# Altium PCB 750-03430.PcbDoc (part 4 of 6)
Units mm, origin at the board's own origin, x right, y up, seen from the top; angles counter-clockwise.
Board outline 141.61 x 63.5 mm, 6 copper layers (Top Layer, L2, L3, L4, L5, Bottom Layer), stack 1.557 mm thick; 401 components, 285 nets, 1356 pads, 1712 vias.
Unrouted connection lines stored in the file: 45.
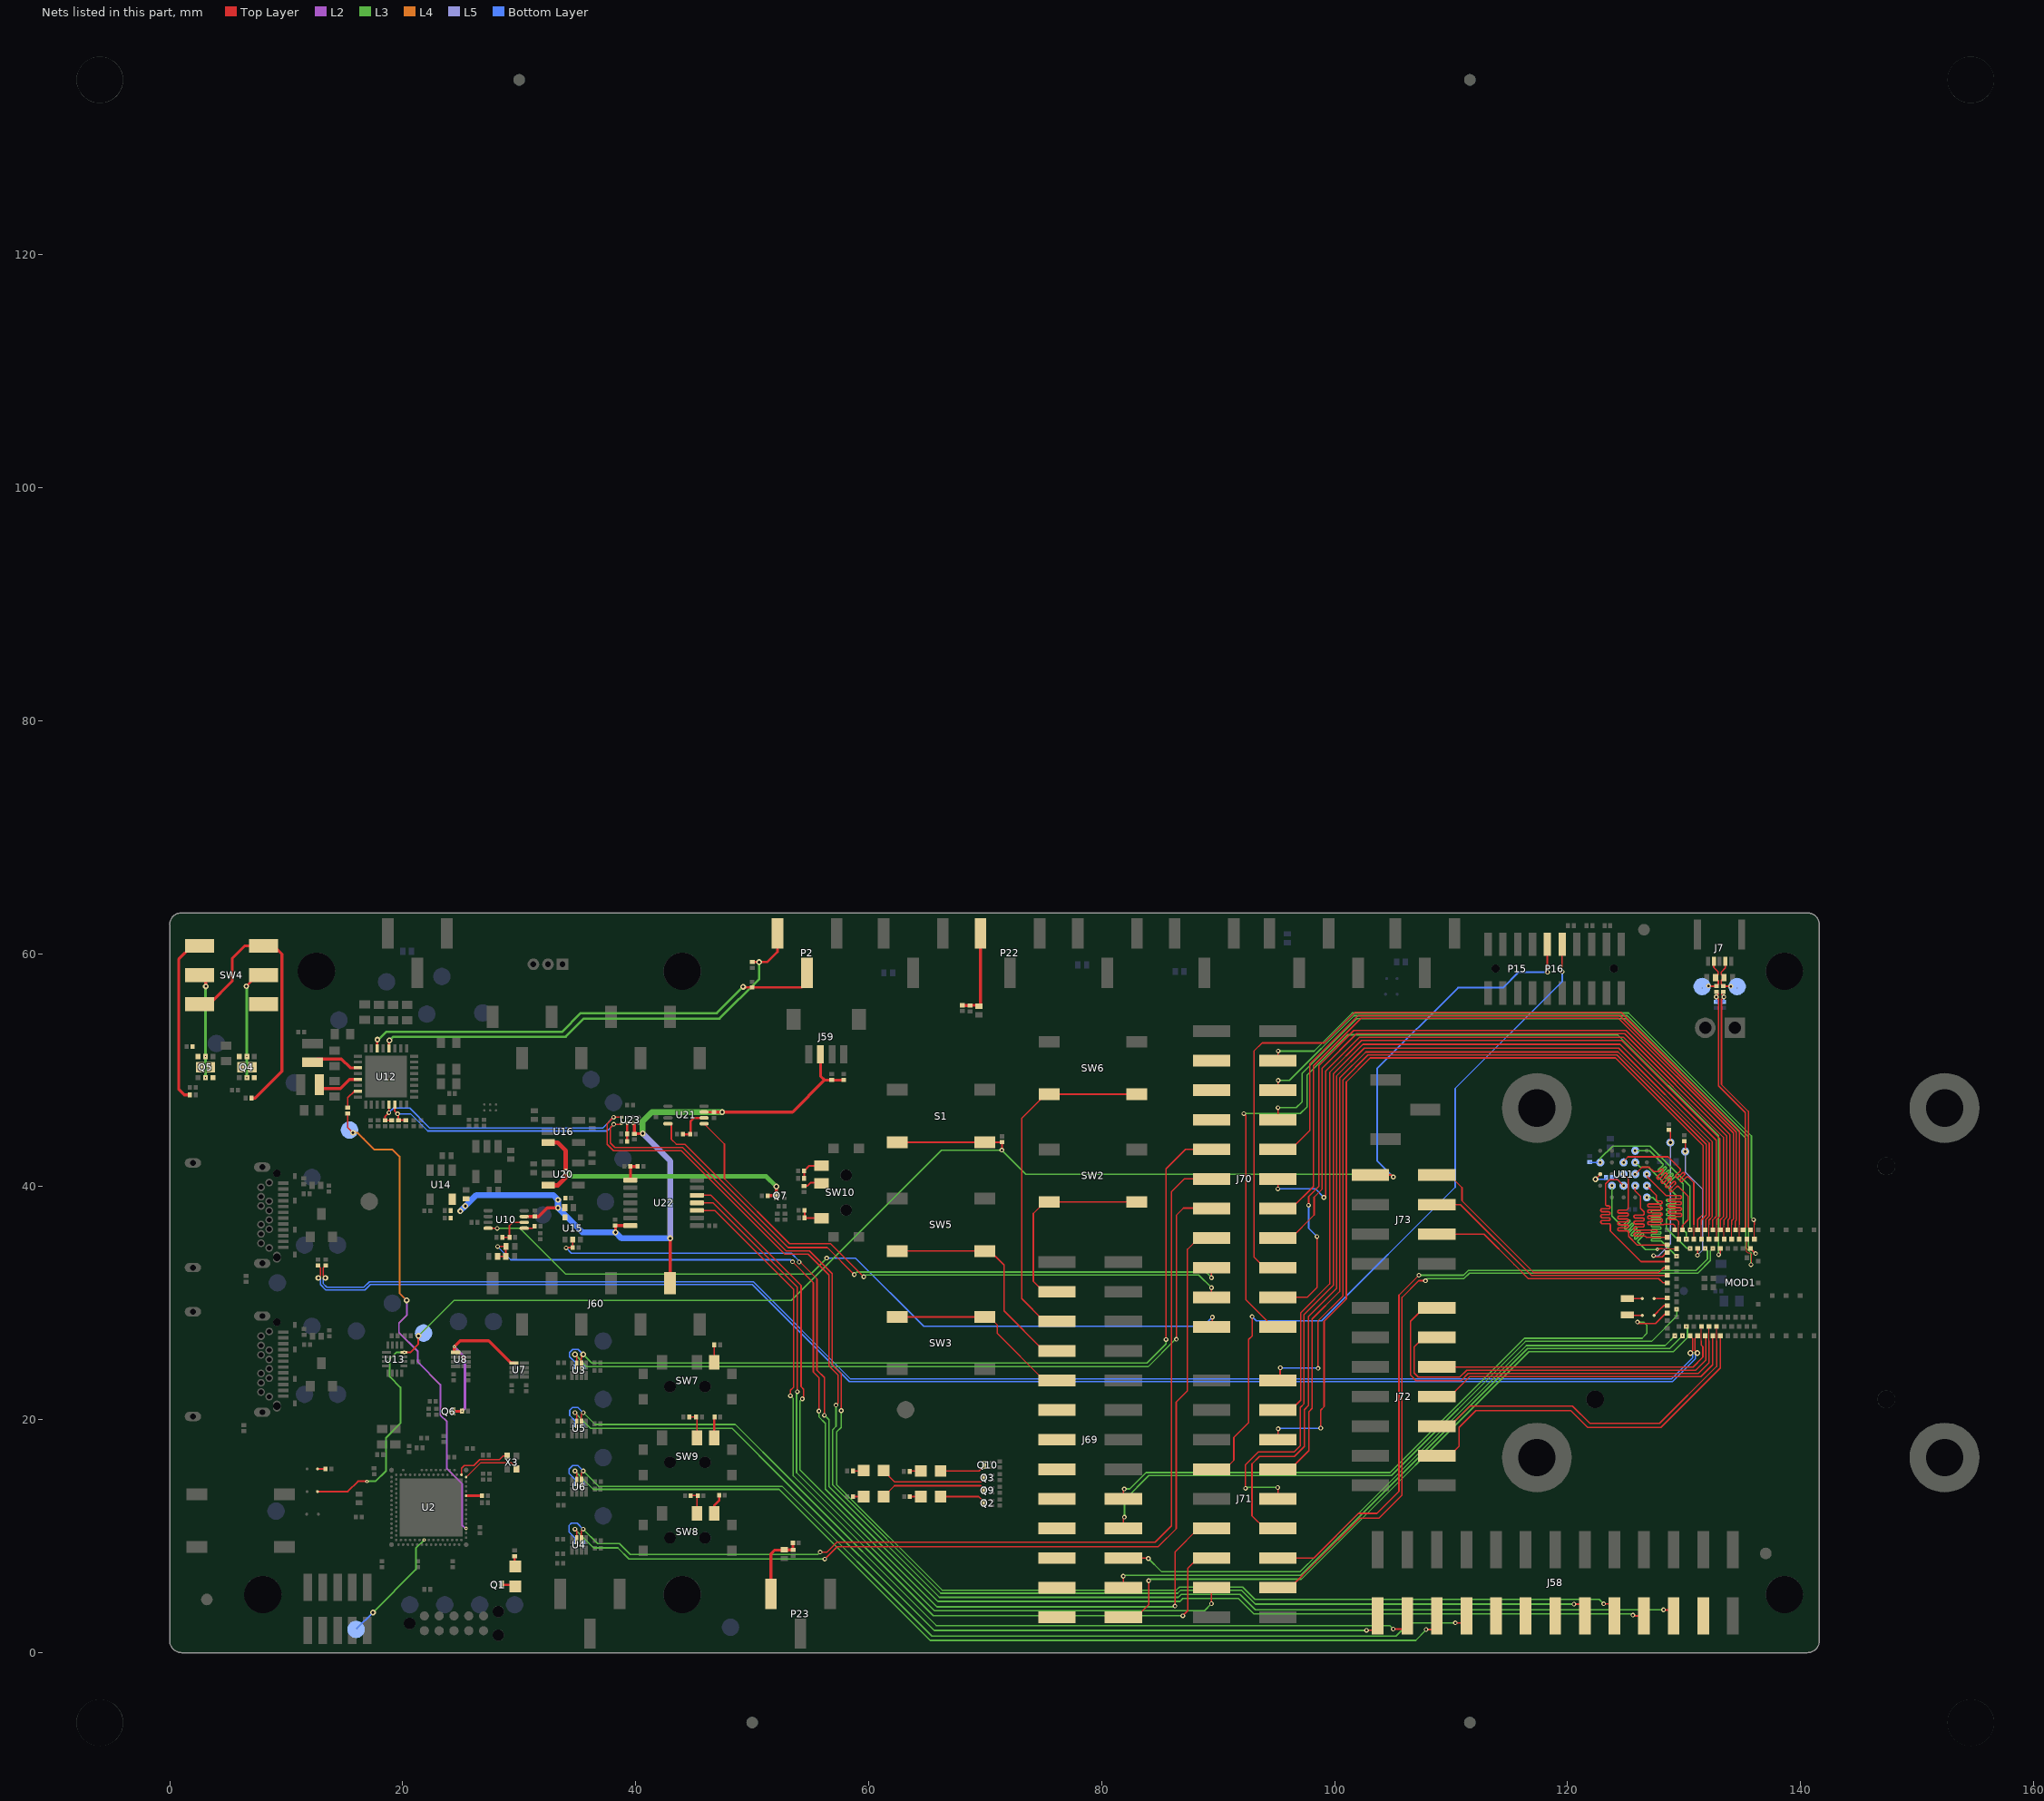
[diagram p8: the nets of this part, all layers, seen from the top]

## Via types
v1: diameter 0.5, hole 0.25, Top Layer to Bottom Layer, tented both sides, 1306 vias
v2: diameter 0.4, hole 0.2, Top Layer to Bottom Layer, tented both sides, 223 vias
v3: diameter 0.3, hole 0.1, Top Layer to L3, tented top, 74 vias
v4: diameter 0.3, hole 0.1, Top Layer to L3, tented both sides, 43 vias
v5: diameter 0.3, hole 0.1, Top Layer to L2, tented both sides, 31 vias
v6: diameter 0.61, hole 0.305, Top Layer to Bottom Layer, tented both sides, 25 vias
v7: diameter 0.3, hole 0.1, Top Layer to L2, tented top, 10 vias

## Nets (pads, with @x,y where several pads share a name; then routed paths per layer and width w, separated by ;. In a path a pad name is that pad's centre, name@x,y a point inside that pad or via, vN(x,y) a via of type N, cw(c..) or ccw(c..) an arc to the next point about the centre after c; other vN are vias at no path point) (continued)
NetJ69_18: J69.18 MOD1.37 | length 56
  Top Layer w0.127: J69.18@81.91,13.161 J69.18@81.868,13.203 81.868,13.977 v2(81.948,14.056) ; v2(125.99,28.376) 126.108,28.258 127.54,28.258 128.432,29.15 MOD1.37@128.559,29.15
  L3 w0.127: v2(81.948,14.056) 82.413,14.056 83.818,15.461 104.768,15.461 116.294,26.987 126.388,26.987 126.811,27.409 126.811,28.117 126.552,28.376 v2(125.99,28.376)
NetJ69_20: J69.20 MOD1.38 | length 57
  Top Layer w0.127: J69.20@81.868,10.663 81.868,11.549 v2(81.96,11.641)
  L3 w0.127: v2(81.96,11.641) 81.96,13.106 84.054,15.2 104.868,15.2 116.389,26.72 127.205,26.72 129.359,28.875 v3(129.359,29.475)
NetJ69_22: J69.22 MOD1.32 | length 56.2
  Top Layer w0.127: J69.22@81.868,8.123 83.968,8.123 v2(84.009,8.081)
  L3 w0.124: v2(84.009,8.081) 85.126,6.965 97.059,6.965 98.426,8.332 116.46,26.365 128.374,26.365 v3(129.209,27.2)
NetJ69_24: J69.24 MOD1.30 | length 57.5
  Top Layer w0.127: v2(81.855,6.562) 81.868,6.549 J69.24@81.868,5.583
  L3 w0.124: v2(81.855,6.562) 81.932,6.638 91.202,6.638 97.092,6.638 116.565,26.111 128.77,26.111 v3(129.859,27.2)
NetJ69_26: J69.26 MOD1.29 | length 60.6
  Top Layer w0.127: J69.26@81.867,3.044 82.95,3.044 84.037,4.132 v2(84.037,6.179)
  L3 w0.124: v2(84.037,6.179) 84.171,6.312 97.144,6.312 116.675,25.844 129.085,25.844 130.29,27.049 130.29,27.894 v3(130.184,28)
NetJ70_4: J70.4 MOD1.88 | length 56.2
  Top Layer w0.076: MOD1.88@136.034,35.5 136.034,36.75
  Top Layer w0.127: J70.4@95.131,50.821 95.131,51.619 v2(95.155,51.642) ; v2(135.962,37.16) 136.031,37.16 136.034,37.157 136.034,36.75
  L3 w0.127: v2(95.155,51.642) 95.158,51.639 98.242,51.639 101.507,54.904 102.547,54.904 125.229,54.904 135.776,44.357 135.776,37.346 v2(135.962,37.16)
NetJ70_6: J70.6 MOD1.86 | length 58.7
  Top Layer w0.102: MOD1.86@135.709,34.7 135.817,34.593 135.817,34.561 136.116,34.261 v2(136.133,34.261)
  Top Layer w0.127: J70.6@95.131,48.281 95.131,49.104 v2(95.156,49.129)
  L3 w0.127: v2(95.156,49.129) 96.122,49.129 101.668,54.675 125.134,54.675 135.532,44.276 135.532,34.845 136.116,34.261 v2(136.133,34.261)
NetJ70_8: J70.8 MOD1.85 | length 63.6
  Top Layer w0.076: MOD1.85@135.384,35.5 135.384,34.414 135.471,34.327 135.616,34.327 135.779,34.165 135.779,33.348 v2(135.739,33.308)
  Top Layer w0.124: J70.8@95.131,45.741 95.131,46.779 v2(95.134,46.782)
  L3 w0.127: v2(95.134,46.782) 96.711,46.782 97.206,47.276 97.206,49.729 101.907,54.429 125.032,54.429 135.297,44.164 135.297,34.746 135.739,34.305 v2(135.739,33.308)
NetJ70_10: J70.10 MOD1.81 | length 60
  Top Layer w0.124: J70.10@95.131,43.201 96.255,43.201 97.869,44.815 97.869,50.552 102.014,54.697 124.466,54.697 134.467,44.695 134.467,37.111 134.409,37.053 MOD1.81@134.409,36.3
NetJ70_12: J70.12 MOD1.75 | length 63
  Top Layer w0.102: MOD1.75@133.109,36.3 133.109,36.75
  Top Layer w0.124: v2(95.127,39.81) 95.131,39.814 J70.12@95.131,40.661 ; v2(99.079,39.081) 99.229,39.23 99.229,49.915 102.152,52.839 124.771,52.839 133.369,44.24 133.369,37.424 133.109,37.164 133.109,36.75
  Bottom Layer w0.124: v2(95.127,39.81) 98.351,39.81 v2(99.079,39.081)
NetJ70_14: J70.14 MOD1.79 | length 64
  Top Layer w0.076: MOD1.79@134.084,35.5 134.084,36.75
  Top Layer w0.124: J70.14@96.28,38.121 98.18,40.021 98.18,50.374 102.265,54.459 124.367,54.459 134.23,44.597 134.23,37.231 134.084,37.085 134.084,36.75
NetJ70_16: J70.16 MOD1.76 | length 65.4
  Top Layer w0.076: MOD1.76@133.434,35.5 133.434,36.75
  Top Layer w0.124: J70.16@95.131,35.581 96.25,35.581 98.243,37.574 98.243,39.105 98.937,39.799 98.937,50.181 101.889,53.133 124.893,53.133 133.664,44.362 133.664,37.383 133.434,37.153 133.434,36.75
NetJ70_18: J70.18 MOD1.82 | length 76.7
  Top Layer w0.076: MOD1.82@134.734,35.5 134.734,36.75
  Top Layer w0.124: J70.18@95.131,33.041 94,33.041 93.069,33.972 93.069,51.629 93.775,52.335 99.11,52.335 101.738,54.963 124.576,54.963 134.734,44.805 134.734,36.75
NetJ70_20: J70.20 MOD1.78 | length 71.9
  Top Layer w0.102: MOD1.78@133.759,36.3 133.759,36.75
  Top Layer w0.124: J70.20@95.131,30.501 97.651,30.501 98.48,31.33 v2(98.48,35.72) ; v2(97.77,38.408) 97.77,39.163 98.639,40.032 98.639,50.387 101.655,53.402 106.388,53.402
  Top Layer w0.127: 106.388,53.402 125.004,53.402 133.933,44.474 133.933,37.306 133.759,37.132 133.759,36.75
  Bottom Layer w0.124: v2(97.77,38.408) 97.77,36.431 v2(98.48,35.72)
NetJ70_22: J70.22 MOD1.74 | length 79.3
  Top Layer w0.102: v2(132.963,34.159) 133.109,34.305 MOD1.74@133.109,34.7
  Top Layer w0.127: v2(92.205,46.271) 92.389,46.087 92.389,30.291 94.719,27.961 J70.22@95.131,27.961
  L3 w0.127: v2(92.205,46.271) 97.054,46.271 97.635,46.852 97.635,49.564 101.112,53.041 124.288,53.041 132.963,44.366 v2(132.963,34.159)
NetJ71_2: J71.2 MOD1.67 | length 73.6
  Top Layer w0.076: MOD1.67@131.484,35.5 131.484,36.75
  Top Layer w0.124: J71.2@95.131,23.364 95.344,23.577 95.323,23.598 v2@95.323,24.476 ; v2@98.556,24.427 98.556,28.468 100.703,30.615
  Top Layer w0.127: 100.703,30.615 100.703,49.145 102.858,51.301 124.223,51.301 131.895,43.629 131.895,37.551 131.484,37.14 131.484,36.75
  Bottom Layer w0.124: v2@95.323,24.476 95.372,24.427 v2@98.556,24.427
  other v2: 98.577,24.406 95.344,24.455
NetJ71_4: J71.4 MOD1.73 | length 78.3
  Top Layer w0.076: MOD1.73@132.784,35.5 132.784,36.75
  Top Layer w0.124: J71.4@95.131,20.824 96.229,20.824 97.083,21.678 97.083,29.173 99.572,31.662 99.572,49.804 102.311,52.543 124.648,52.543 133.074,44.118 133.074,37.455 132.784,37.165 132.784,36.75
NetJ71_6: J71.6 MOD1.66 | length 77.3
  Top Layer w0.102: MOD1.66@131.159,36.3 131.159,36.75
  Top Layer w0.124: J71.6@95.131,18.284 v2@95.131,19.243 ; 101.004,30.358 101.004,48.993 103.059,51.048 124.119,51.048 131.642,43.525 131.642,37.65 131.159,37.167 131.159,36.75
  Top Layer w0.127: v2(98.799,19.275) 98.799,20.814 99.098,21.113 99.098,28.452 101.004,30.358
  Bottom Layer w0.124: v2@95.14,19.252 98.776,19.252 v2(98.799,19.275)
  other v2: 95.152,19.222
NetJ71_8: J71.8 MOD1.69 | length 79.8
  Top Layer w0.102: MOD1.69@131.865,36.3 131.865,36.75
  Top Layer w0.127: J71.8@95.131,15.744 96.194,15.744 97.795,17.346 97.795,20.686 98.074,20.964 98.074,28.648 100.427,31.001 100.427,49.308 102.679,51.56 124.331,51.56 132.154,43.737 132.154,37.472 131.865,37.183 131.865,36.75
NetJ71_10: J71.10 MOD1.72 | length 89.4
  Top Layer w0.102: MOD1.72@132.459,36.3 132.459,36.75
  Top Layer w0.124: v2(92.349,14.109) 92.328,14.13 92.328,16.114 93.434,17.221 96.513,17.221 97.053,17.76 97.053,21.051 97.377,21.376 97.377,29.029 99.882,31.534 99.882,49.664 102.436,52.218 124.514,52.218 132.749,43.983 132.749,37.442 132.459,37.152 132.459,36.75 ; v2@95.095,14.195 95.131,14.16 J71.10@95.131,13.204
  L3 w0.124: v2(92.349,14.109) 92.434,14.195 v2@95.095,14.195
  other v2: 95.116,14.174
NetJ71_12: J71.12 MOD1.70 | length 90.2
  Top Layer w0.076: MOD1.70@132.134,35.5 132.134,36.75
  Top Layer w0.124: J71.12@95.131,10.664 93.995,10.664 92.907,11.752 92.907,16.2 93.551,16.844 96.554,16.844 97.407,17.697 97.407,20.863 97.74,21.196 97.74,28.844 100.154,31.258 100.154,49.503 102.545,51.893 124.379,51.893 132.424,43.848 132.424,37.429 132.134,37.139 132.134,36.75
NetJ71_14: J71.14 MOD1.68 | length 58.4
  Top Layer w0.124: J71.14@95.131,8.124 98.21,8.124 102.046,11.96
  Top Layer w0.127: 102.046,11.96 103.642,11.96 105.52,13.838 105.52,30.689 v2(107.232,32.402)
  L3 w0.127: v2(107.232,32.402) 111.065,32.402 111.475,32.811 114.795,32.811 131.026,32.811 132.004,33.789 132.004,34.505 v3(131.809,34.7)
NetJ71_16: J71.16 MOD1.71 | length 59.8
  Top Layer w0.127: J71.16@95.131,5.584 96.2,5.584 98.362,7.746 102.167,11.551 103.812,11.551 105.788,13.527 105.788,30.497 107.22,31.929 v2(107.799,31.929)
  L3 w0.127: v2(107.799,31.929) 107.967,32.096 111.085,32.096 111.57,32.582 114.7,32.582 131.177,32.582 132.251,33.656 132.251,34.492 v3(132.459,34.7)
NetJ72_2: J72.2 MOD1.20 | length 36.9
  Top Layer w0.076: 132.134,26.75 MOD1.20@132.134,28
  Top Layer w0.127: J72.2@108.77,29.604 107.674,29.604 106.507,28.438 106.507,23.838 106.992,23.353 110.852,23.353 111.47,23.971 131.218,23.971 132.134,24.887 132.134,26.75
NetJ72_4: J72.4 MOD1.22 | length 32.4
  Top Layer w0.102: MOD1.22@131.809,27.2 131.858,27.151 MOD1.22@131.858,27
  Top Layer w0.127: J72.4@108.77,27.064 107.654,27.064 106.833,26.243 106.833,24.003 107.173,23.662 110.744,23.662 111.333,24.252 130.99,24.252 131.858,25.12 MOD1.22@131.858,27
NetJ72_6: J72.6 MOD1.23 | length 25.9
  Top Layer w0.076: 131.484,26.75 MOD1.23@131.484,28
  Top Layer w0.124: J72.6@108.77,24.524 130.771,24.524 131.608,25.362
  Top Layer w0.127: 131.484,26.75 131.484,26.401 131.608,26.277 131.608,25.362
NetJ72_8: J72.8 MOD1.19 | length 27.3
  Top Layer w0.102: 132.459,26.75 MOD1.19@132.459,27.2
  Top Layer w0.127: J72.8@108.77,21.984 109.888,21.984 110.939,23.036 111.599,23.695 131.435,23.695 132.459,24.719 132.459,26.75
NetJ72_10: J72.10 MOD1.17 | length 30.8
  Top Layer w0.076: 132.784,26.75 MOD1.17@132.784,28
  Top Layer w0.127: J72.10@108.77,19.444 109.88,19.444 111.599,21.163 120.422,21.163 121.908,19.677 127.895,19.677 132.784,24.566 132.784,26.75
NetJ72_12: J72.12 MOD1.16 | length 32.4
  Top Layer w0.102: 133.109,26.75 MOD1.16@133.109,27.2
  Top Layer w0.127: J72.12@108.77,16.904 109.872,16.904 110.689,17.722 110.689,19.345 112.121,20.777 120.273,20.777 121.725,19.324 128.002,19.324 133.109,24.432 133.109,26.75
NetJ73_2: J73.2 MOD1.49 | length 24.1
  Top Layer w0.124: 110.935,39.915 110.935,38.79 117.087,32.638
  Top Layer w0.127: J73.2@108.77,40.999 109.851,40.999 110.935,39.915 ; 117.087,32.638 127.822,32.638 128.234,33.05 MOD1.49@128.559,33.05
NetJ73_4: J73.4 MOD1.47 | length 22.3
  Top Layer w0.127: J73.4@108.77,38.459 110.809,38.459 116.891,32.377 128.109,32.377 128.536,32.377 MOD1.47@128.559,32.4
NetJ73_6: J73.6 MOD1.45 | length 21.5
  Top Layer w0.124: 115.408,33.327 116.623,32.112
  Top Layer w0.127: J73.6@108.77,35.919 112.816,35.919 115.408,33.327 ; 116.623,32.112 127.817,32.112 128.179,31.75 MOD1.45@128.559,31.75
NetL7_2: L7.2 U12.3 | length 4.3
  Top Layer w0.254: L7.2@12.324,50.591 12.686,50.953 14.751,50.953 15.504,50.201 U12.3@16.174,50.201
NetL10_2: L10.2 U12.5 | length 3.8
  Top Layer w0.254: L10.2@12.709,48.425 14.662,48.425 15.437,49.2 U12.5@16.174,49.2
NetLED1_1: LED1.1 R5.1 | length 1
  Top Layer w0.2: LED1.1@29.611,7.262 R5.1@29.611,8.258
NetLED1_2: LED1.2 Q1.3 | length 1.1
  Top Layer w0.2: Q1.3@28.514,5.825 28.527,5.812 LED1.2@29.611,5.812
NetLED2_1: LED2.1 R20.1 | length 0.9
  Top Layer w0.127: R20.1@63.541,13.403 63.546,13.397 LED2.1@64.472,13.397
NetLED2_2: LED2.2 Q2.3 | length 4
  Top Layer w0.127: LED2.2@66.172,13.397 69.442,13.397 69.886,12.954 Q2.3@69.886,12.836
NetLED3_1: LED3.1 R21.1 | length 0.9
  Top Layer w0.152: R21.1@58.651,15.597 59.546,15.597 LED3.1@59.582,15.633
NetLED3_2: LED3.2 Q3.3 | length 9.2
  Top Layer w0.127: LED3.2@61.282,15.633 61.282,15.609 62.242,14.649 69.635,14.649 69.886,14.9 Q3.3@69.886,15.017
NetLED4_1: LED4.1 R68.1 | length 0.9
  Top Layer w0.152: R68.1@58.651,13.403 59.577,13.403 LED4.1@59.582,13.397
NetLED4_2: LED4.2 Q9.3 | length 9.3
  Top Layer w0.127: LED4.2@61.282,13.397 62.214,14.329 69.645,14.329 69.886,14.089 Q9.3@69.886,13.926
NetLED5_1: LED5.1 R69.1 | length 1
  Top Layer w0.152: R69.1@63.522,15.564 63.555,15.597 LED5.1@64.472,15.597
NetLED5_2: LED5.2 Q10.3 | length 4
  Top Layer w0.127: LED5.2@66.172,15.597 69.484,15.597 69.886,15.998 Q10.3@69.886,16.108
NetMOD1_39: MOD1.39 SB6.2 | length 1.5
  Top Layer w0.102: 128.109,29.644 128.266,29.8 MOD1.39@128.559,29.8
  Top Layer w0.127: SB6.2@127.418,28.953 128.109,29.644
NetMOD1_41: MOD1.41 SB7.2 | length 1.2
  Top Layer w0.102: 128.109,30.394 128.503,30.394 MOD1.41@128.559,30.45
  Top Layer w0.127: SB7.2@127.418,30.394 128.109,30.394
NetP2_2: P2.2 R105.1 U12.30 | length 40.5
  Top Layer w0.203: U12.30@17.823,51.85 17.823,52.615 v1(17.829,52.62) ; v1(49.22,57.156) 49.284,57.092 R105.1@49.988,57.092 54.238,57.092 54.716,57.57 P2.2@54.716,58.355
  L3 w0.203: v1(17.829,52.62) 17.922,52.62 18.589,53.286 33.661,53.286 35.263,54.888 46.953,54.888 v1(49.22,57.156)
NetP2_3: P2.3 R88.1 U12.28 | length 40.2
  Top Layer w0.203: U12.28@18.824,51.85 18.824,52.513 v1(18.858,52.546) ; R88.1@50.009,59.269 50.012,59.272 v1(50.594,59.272) 51.292,59.272 52.176,60.156 P2.3@52.176,61.755
  L3 w0.203: v1(18.858,52.546) 19.183,52.871 33.99,52.871 35.541,54.422 47.196,54.422 50.613,57.84 50.613,59.254 v1(50.594,59.272)
NetP22_3: P22.3 R35.1 R97.2 R101.1 | length 7.7
  Top Layer w0.254: R101.1@68.048,55.569 68.057,55.559 R97.2@68.709,55.559 ; R97.2@68.721,55.571 69.392,55.571 R35.1@69.462,55.501 69.597,55.636 P22.3@69.597,61.755
NetP23_3: P23.3 R37.1 R98.2 R102.1 | length 6.1
  Top Layer w0.254: P23.3@51.605,5.034 51.605,8.471 51.942,8.807 52.732,8.807 R37.1@52.757,8.832 R98.2@53.505,8.832 ; R102.1@53.499,9.431 53.499,8.838 R98.2@53.505,8.832 ; R98.2@53.524,8.812 R98.2@53.505,8.832
NetQ4_2: Q4.2 Q4.5 SW4.5 | length 9.8
  Top Layer w0.254: v1(6.578,57.202) 7.545,58.169 SW4.5@8.072,58.169
  L3 w0.254: v1(6.578,57.202) 6.624,57.157 v3(6.624,51.162) v3(6.624,49.352)
NetQ4_3: Q4.3 Q4.6
NetQ5_2: Q5.2 Q5.5 SW4.2 | length 9
  Top Layer w0.254: SW4.2@2.572,58.169 3.102,57.639 v1(3.102,57.193)
  L3 w0.254: v3(3.075,49.353) v3(3.075,51.163) 3.075,57.166 v1(3.102,57.193)
NetQ5_3: Q5.3 Q5.6 R27.1 SW4.6
NetQ6_3: Q6.3 R19.1 U7.5 U8.5 | length 13.5
  Top Layer w0.125: R19.1@25.059,20.717 R19.1@25.086,20.743
  Top Layer w0.254: Q6.3@24.321,20.717 R19.1@25.059,20.717 ; U8.5@24.545,25.771 24.426,25.89 v5(24.426,26.265) 24.94,26.778 27.374,26.778 29.288,24.864 U7.5@29.545,24.864
  L2 w0.254: v5@24.413,26.265 25.342,25.336 25.342,20.985 v5(25.086,20.73)
NetQ7_3: Q7.3 R36.2 U16.3 U20.3 | length 26
  Top Layer w0.254: R36.2@51.353,39.223 51.356,39.226 Q7.3@52.072,39.226 52.072,39.999 v1(52.079,40.007)
  Top Layer w0.381: U20.3@32.487,40.123 33.328,40.123 33.997,40.792 v1(33.997,41.286) 33.997,43.091 33.298,43.79 U16.3@32.496,43.79
  L3 w0.381: v1(33.997,41.286) 34.394,40.89 51.197,40.89 v1(52.079,40.007)
NetR7_1: R7.1 U2.L31 | length 1.3
  Top Layer w0.2: U2.L31@25.445,13.474 R7.1@26.76,13.474
NetR12_1: R12.1 SW8.3 | length 1.7
  Top Layer w0.203: SW8.3@46.753,11.961 46.753,12.653 47.157,13.056 R12.1@47.157,13.505
NetR13_1: R13.1 SW9.3 | length 1.8
  Top Layer w0.203: SW9.3@46.753,18.441 R13.1@46.753,20.211
NetR14_1: R14.1 R118.1 SW10.3 | length 2.3
  Top Layer w0.15: R118.1@54.465,40.71 R14.1@54.465,41.355 54.901,41.791 SW10.3@55.969,41.791
NetR22_2: R22.2 SB1.2 | length 0.7
  Top Layer w0.15: SB1.2@12.682,15.773 SB1.2@12.682,15.773 R22.2@13.385,15.772
NetR26_2: R26.2 SW4.3 SW4.4 | length 24.2
  Top Layer w0.254: SW4.3@2.572,55.669 3.391,55.669 5.371,57.649 5.371,59.612 6.427,60.669 SW4.4@8.072,60.669 8.939,60.669 9.641,59.967 9.641,49.907 7.345,47.612 R26.2@7.016,47.612
NetR28_1: R28.1 U11.A3 | length 1.6
  Top Layer w0.127: v1(122.388,40.639) 122.803,41.055 U11.A3@122.803,41.079
  Bottom Layer w0.127: v1(122.388,40.639) 123.167,40.639 R28.1@123.313,40.785
NetR38_1: R38.1 SW7.3 | length 1.5
  Top Layer w0.127: R38.1@46.739,26.421 46.753,26.407 SW7.3@46.753,24.937
NetR64_1: R64.1 SW4.1 | length 14.6
  Top Layer w0.254: R64.1@1.719,47.878 1.255,47.878 0.783,48.351 0.783,59.544 1.908,60.669 SW4.1@2.572,60.669
NetR75_1: R75.1 R80.1 U10.6 | length 3
  Top Layer w0.127: R75.1@28.571,35.648 R80.1@29.164,35.648 29.164,36.649 29.45,36.936 U10.6@30.431,36.936
NetR76_1: R76.1 R92.1 U21.6 | length 3
  Top Layer w0.203: R76.1@44.068,44.502 R92.1@44.662,44.502 44.709,44.549 44.709,45.619 44.996,45.905 U21.6@45.871,45.905
NetR77_1: R77.1 R93.1 U22.8 | length 1.8
  Top Layer w0.254: U22.8@39.554,40.561 39.554,41.731 R93.1@39.551,41.735 R77.1@40.171,41.735
NetR78_1: R78.1 R94.1 U23.C2 | length 1.6
  Top Layer w0.203: R94.1@39.269,43.898 39.263,43.904 R78.1@39.263,44.528 39.273,44.538 U23.C2@39.273,45.468
NetR109_1: R109.1 R110.1 SW8.2 | length 2.1
  Top Layer w0.127: R109.1@44.736,13.485 R110.1@45.326,13.485 45.253,13.412 SW8.2@45.253,11.961
NetR111_1: R111.1 R112.1 SW9.2 | length 2.4
  Top Layer w0.127: R111.1@44.597,20.226 R112.1@45.188,20.226 45.253,20.161 SW9.2@45.253,18.441
NetR113_1: R113.1 SW10.2 | length 1.7
  Top Layer w0.15: R113.1@54.447,40.058 54.722,40.058 55.021,40.357 55.903,40.357 SW10.2@55.969,40.291
NetR117_1: R117.1 R119.1 SW10.1 | length 2.1
  Top Layer w0.15: R117.1@54.504,37.973 54.508,37.969 R119.1@54.508,37.319 54.536,37.291 SW10.1@55.969,37.291
NetR120_2: R120.2 U12.7 | length 2
  Top Layer w0.152: R120.2@15.28,46.793 15.28,47.633 15.846,48.199 U12.7@16.174,48.199
NetR122_2: R122.2 U10.5 | length 1
  Top Layer w0.127: U10.5@30.431,36.436 31.153,36.436 R122.2@31.326,36.609
NetSB6_1: SB6.1 X2.2 | length 1.3
  Top Layer w0.127: X2.2@125.122,29.003 125.173,28.953 SB6.1@126.418,28.953
NetSB7_1: SB7.1 X2.1 | length 1.3
  Top Layer w0.127: X2.1@125.122,30.403 125.132,30.394 SB7.1@126.418,30.394
NetTP40_1: TP40.1 U2.AK14 | length 10
  L3 w0.152: v1@17.445,3.454 21.132,7.141 21.132,8.961 v3(21.845,9.674)
  Bottom Layer w0.152: TP40.1@16.066,2.069 v1@17.447,3.45
  other v1: 17.447,3.454
NetU2_B30: U2.B30 X3.3 | length 4.9
  Top Layer w0.125: U2.B30@25.045,15.274 25.045,15.822 25.284,16.062 26.103,16.062 26.603,16.562 28.303,16.562 28.62,16.879 X3.3@28.97,16.879
NetU2_C31: U2.C31 X3.1 | length 5.3
  Top Layer w0.125: U2.C31@25.445,15.074 25.469,15.074 26.707,16.312 29.304,16.312 29.945,15.671 X3.1@29.945,15.604
NFC1: C65.1 J7.2 R24.1 TP19.1 | length 3.1
  Top Layer w0.127: C65.1@133.343,58.051 133.183,58.211 133.183,58.407 133.548,58.772 J7.2@133.548,59.341 ; C65.1@133.418,57.942 133.19,57.714 133.19,57.373 R24.1@133.355,57.209 133.371,57.224 133.394,57.2 v2(134.004,57.2)
  Bottom Layer w0.127: TP19.1@134.537,57.053 TP19.1@134.542,57.053
NFC2: C66.1 J7.4 R25.1 TP20.1 | length 3.1
  Top Layer w0.127: v2(132.096,57.238) 132.125,57.209 R25.1@132.791,57.209 132.936,57.353 132.936,57.704 C66.1@132.699,57.942 ; J7.4@132.548,59.341 132.548,58.817 132.929,58.436 132.929,58.201 C66.1@132.779,58.051
  Bottom Layer w0.127: TP20.1@131.542,57.053 TP20.1@131.552,57.053
nPM1300_R\E\S\E\T\: R120.1 TP11.1 U2.AE31 | length 41.5
  Top Layer w0.152: R120.1@15.28,46.293 15.28,45.082 v1(15.738,44.624)
  L2 w0.152: v1@20.366,30.226 20.366,28.981 19.68,28.296 19.68,27.483 21.306,25.857 21.306,24.943 23.236,23.012 23.236,20.399 23.794,19.841 23.794,15.79 25.116,14.468 25.116,10.922 25.363,10.674 v7(25.445,10.674)
  L4 w0.152: v1(15.738,44.624) 16.139,44.624 16.66,44.103 17.586,43.176 19.131,43.176 19.723,42.584 19.723,30.867 v1(20.335,30.254)
nRF54_N: MOD1.28 R43.1 | length 126
  Top Layer w0.119: v1@13.315,32.22 13.169,32.366 13.169,33.018 R43.1@13.388,33.237 ; MOD1.28@130.509,27.2 130.724,26.986 130.724,25.912 v1@130.585,25.773
  Bottom Layer w0.119: v1@13.315,32.22 13.166,32.071 13.166,31.688 13.492,31.362 16.672,31.362 17.14,31.83 50.105,31.83 58.444,23.492 128.91,23.492 130.73,25.312 130.73,25.628 v1@130.585,25.773
  other v1: 130.538,25.726 13.363,32.167
nRF54_P: MOD1.25 R44.1 | length 126.7
  Top Layer w0.119: R44.1@12.73,33.237 12.948,33.018 12.948,32.364 v1@12.804,32.22 ; v1@131.096,25.773 130.945,25.925 130.945,26.986 MOD1.25@131.159,27.2
  Bottom Layer w0.119: v1@12.804,32.22 12.945,32.079 12.945,31.597 13.401,31.141 16.764,31.141 17.232,31.61 50.014,31.61 58.352,23.271 129.001,23.271 130.951,25.221 130.951,25.628 v1@131.096,25.773
  other v1: 131.138,25.726 12.762,32.167
nRF54H20_RESET: C9.1 J73.1 P15.10 P16.10 S1.3 S1.4 SB3.2 TP61.1 U13.12 | length 154.2
  Top Layer w0.152: SB3.2@12.682,13.831 15.284,13.831 16.17,14.717 v3@16.926,14.717 ; v4(20.141,25.777) 20.645,25.777 21.351,26.484 v1(21.351,27.189) ; S1.3@62.462,43.814 S1.4@69.962,43.814 71.457,43.814 C9.1@71.458,43.815 71.458,43.162 v2(71.431,43.136) ; J73.1@103.07,40.999 104.879,40.999 105.037,40.841 v2(105.037,40.83) ; P15.10@118.256,60.816 118.256,58.433 v2(118.278,58.411)
  L3 w0.127: v1(21.351,27.189) 24.41,30.249 53.358,30.249 66.245,43.136 v2(71.431,43.136)
  L3 w0.152: v3@16.926,14.717 v3(16.937,14.707) 17.673,14.707 18.57,15.603 18.57,18.448 19.807,19.685 19.807,22.775 18.893,23.689 18.893,25.222 19.448,25.777 v4(20.141,25.777) ; v2(71.431,43.136) 73.503,41.065 104.813,41.065 105.037,40.841 v2(105.037,40.83)
  Bottom Layer w0.152: v2(105.037,40.83) 103.65,42.217 103.65,50.138 110.593,57.08 114.466,57.08 115.797,58.411 v2(118.278,58.411)
P0.00: J69.23
P0.01: J69.17
P0.02: J69.19
P0.03: J69.21
P0.04: J69.25
P0.05: J69.11
P0.06: J69.15
P0.07: J69.13
P0.08: J69.3 SW2.3 SW2.4 | length 17.5
  Top Layer w0.127: J69.3@76.168,30.983 75.026,30.983 74.134,31.875 74.134,37.698 75.123,38.687 SW2.3@75.504,38.687 SW2.4@83.004,38.687
P0.09: J69.9 SW3.3 SW3.4 | length 16.7
  Top Layer w0.127: SW3.4@62.462,28.815 SW3.3@69.962,28.815 70.349,28.815 71.054,28.11 71.054,27.386 75.077,23.363 J69.9@75.856,23.363 ; J69.9@75.856,23.363 J69.9@76.168,23.363 J69.9@75.856,23.363
P0.10: J69.7 SW5.3 SW5.4 | length 20.7
  Top Layer w0.127: SW5.3@62.462,34.476 SW5.4@69.962,34.476 70.423,34.476 71.621,33.278 71.621,29.337 75.055,25.903 J69.7@76.168,25.903 75.829,25.903 J69.7@75.057,25.903
P0.11: J69.5 SW6.3 SW6.4 | length 31.1
  Top Layer w0.127: J69.5@75.083,28.443 75.855,28.443 J69.5@76.168,28.443 75.075,28.443 73.133,30.385 73.133,45.871 75.198,47.937 SW6.3@75.504,47.937 SW6.4@83.004,47.937
P1.00: C21.2 J58.8 R33.1 R48.2 | length 123.8
  Top Layer w0.124: v2(28.147,34.856) 28.173,34.882 C21.2@28.868,34.882 28.852,34.866 R48.2@28.852,34.011 28.842,34.022 R33.1@28.148,34.022 ; 55.254,24.082 55.724,23.612 v2(55.724,20.735) ; v2(125.608,3.23) 125.682,3.156 J58.8@126.558,3.156
  Top Layer w0.125: v2(53.46,33.561) 55.254,31.768 55.254,24.082
  L3 w0.124: v2(55.724,20.735) 55.724,20.255 56.291,19.688 56.291,14.049 65.935,4.406 86.727,4.406 86.972,4.651 91.73,4.651 93.06,3.321 125.516,3.321 v2(125.608,3.23)
  Bottom Layer w0.125: v2(28.147,34.856) 29.282,33.721 53.301,33.721 v2(53.46,33.561)
P1.01: J58.6 R87.2 U15.2 | length 119.8
  Top Layer w0.124: v2(34.032,34.746) 34.058,34.773 R87.2@34.6,34.773 34.598,34.774 U15.2@34.598,35.467 ; v2(54.035,33.527) 54.117,33.527 55.563,32.082 55.563,24.244 56.199,23.608 v2(56.199,20.379) ; v2(128.228,3.686) 128.249,3.664 129.098,3.664 J58.6@129.098,3.156
  L3 w0.124: v2(56.199,20.379) 56.587,19.991 56.587,14.249 66.08,4.756 86.587,4.756 86.832,5.002 91.875,5.002 93.191,3.686 v2(128.228,3.686)
  Bottom Layer w0.124: v2(34.032,34.746) 34.486,34.292 53.352,34.292 54.035,33.609 v2(54.035,33.527)
P1.02: J58.4 | length 1.2
  Top Layer w0.124: J58.4@131.519,4.331 131.638,4.212 J58.4@131.638,3.156
P1.03: J58.10 R99.2 R107.2 U12.14 U23.D2 | length 138.3
  Top Layer w0.124: v2(123.086,4.199) 123.814,4.199 124.018,3.996 J58.10@124.018,3.156
  Top Layer w0.127: U23.D2@38.773,45.468 38.659,45.354 v2(38.117,45.354) 37.829,45.066 37.829,43.755 38.224,43.36 44.034,43.36 52.908,34.486 54.93,34.486 56.869,32.547 56.869,24.724 57.647,23.946 v2(57.647,20.774)
  Top Layer w0.15: U12.14@19.325,47.05 19.324,46.494 v2(19.563,46.255) 19.63,46.189 R107.2@19.63,45.709 ; R107.2@19.642,45.697 19.649,45.705 R99.2@20.266,45.705
  L3 w0.124: v2(57.647,20.774) 57.647,19.346 57.259,18.958 57.259,14.417 66.307,5.369 86.407,5.369 86.677,5.638 92.105,5.638 93.162,4.582 122.547,4.582 122.704,4.582 v2(123.086,4.199)
  Bottom Layer w0.127: v2(19.563,46.255) 20.681,46.255 22.152,44.784 37.547,44.784 v2(38.117,45.354)
P1.04: J58.12 R100.2 R106.1 U12.13 U23.D1 | length 138.1
  Top Layer w0.124: v2(120.545,4.171) J58.12@121.477,4.171 ; J58.12@121.478,3.156 J58.12@121.478,4.171
  Top Layer w0.127: U23.D1@38.773,45.968 38.115,45.968 v2(38.105,45.959) 37.547,45.4 37.547,43.639 38.107,43.078 43.917,43.078 52.791,34.204 54.813,34.204 56.587,32.43 56.587,24.607 57.366,23.827 57.366,21.422 v2@57.212,21.268
  Top Layer w0.15: U12.13@18.824,47.05 18.824,46.361 v2(18.812,46.348) 18.502,46.039 18.502,45.692 18.509,45.699 R106.1@19.061,45.699
  L3 w0.124: v2@57.212,21.268 v2(57.196,21.252) 57.196,19.429 56.917,19.149 56.917,14.38 66.196,5.101 86.519,5.101 86.788,5.37 91.994,5.37 93.194,4.171 v2(120.545,4.171)
  Bottom Layer w0.127: v2(18.812,46.348) 19.203,46.74 20.607,46.74 22.307,45.04 37.187,45.04 v2(38.105,45.959)
P1.05: J58.14
P1.06: J58.16
P1.07: J58.20 R59.1 U6.6 | length 86.7
  Top Layer w0.124: U6.6@35.345,14.696 35.345,15.443 v2(35.5,15.599) ; v2(110.357,2.568) 110.386,2.539 111.111,2.539 111.318,2.745 J58.20@111.318,3.156
  L3 w0.124: v2(35.5,15.599) 36.814,14.285 52.563,14.285 65.424,1.424 105.266,1.424 106.41,2.568 v2(110.357,2.568)
  Bottom Layer w0.124: R59.1@34.817,14.459 34.817,14.855 34.288,15.384 34.288,15.763 34.587,16.062 35.037,16.062 v2(35.5,15.599)
P1.08: J58.18
P1.09: J58.22 R58.1 U6.7 | length 84
  Top Layer w0.124: v2(34.789,15.599) 34.945,15.443 U6.7@34.945,14.696 ; v2(107.846,1.986) 108.788,1.986 108.788,3.145 J58.22@108.778,3.156
  L3 w0.124: v2(34.789,15.599) 36.364,14.024 52.301,14.024 65.271,1.054 106.959,1.054 107.846,1.941 v2(107.846,1.986)
  Bottom Layer w0.124: v2(34.789,15.599) 35.471,14.917 R58.1@35.471,14.455
P1.10: J58.24 R57.1 U5.6 | length 83.4
  Top Layer w0.124: v2(105.026,2.025) 106.112,2.025 106.238,2.151 J58.24@106.238,3.156
  Top Layer w0.127: U5.6@35.345,19.696 35.345,20.443 v2(35.5,20.599)
  L3 w0.124: v2(35.5,20.599) 36.513,19.587 48.549,19.587 53.207,14.929 65.801,2.334 104.716,2.334 v2(105.026,2.025)
  Bottom Layer w0.127: R57.1@34.827,19.527 34.827,19.884 34.34,20.372 34.34,20.815 34.575,21.051 35.049,21.051 v2(35.5,20.599)
P1.11: J58.26 R56.1 U5.7 | length 80.1
  Top Layer w0.124: v2(102.739,1.917) 103.551,1.917 103.699,2.065 J58.26@103.699,3.157
  Top Layer w0.127: v2(34.789,20.599) 34.945,20.443 U5.7@34.945,19.696
  L3 w0.124: v2(34.789,20.599) 36.13,19.258 48.274,19.258 52.905,14.627 65.624,1.908 102.73,1.908 v2(102.739,1.917)
  Bottom Layer w0.127: v2(34.789,20.599) 35.466,19.922 R56.1@35.466,19.527
P2.00: J70.5 | length 0.6
  Top Layer w0.127: J70.5@89.018,48.694 J70.5@89.431,48.281
P2.01: J70.3 | length 1.1
  Top Layer w0.125: J70.3@88.338,50.821 J70.3@89.431,50.821
P2.02: J70.7 | length 1.1
  Top Layer w0.127: J70.7@88.334,45.741 J70.7@89.431,45.741
P2.03: J70.21 U10.4 | length 68
  Top Layer w0.127: U10.4@27.331,36.436 28.09,36.436 v2(28.109,36.417) ; J70.21@89.431,27.961 89.506,28.036 v2(89.506,28.802)
  L3 w0.127: v2(28.109,36.417) 30.074,36.417 33.99,32.501 55.03,32.501 v2(56.395,33.866)
  Bottom Layer w0.127: v2(56.395,33.866) 58.878,33.866 64.731,28.014 88.718,28.014 v2(89.506,28.802)
P2.04: J70.9 R53.1 U3.6 | length 74.5
  Top Layer w0.125: U3.6@35.345,24.696 35.345,25.443 v1(35.5,25.599) ; v2(85.53,26.876) 85.53,41.529 87.202,43.201 J70.9@89.431,43.201
  L3 w0.125: v1(35.5,25.599) 36.234,24.865 83.888,24.865 85.53,26.507 v2(85.53,26.876)
  Bottom Layer w0.125: R53.1@34.842,24.535 34.842,24.903 34.324,25.421 34.324,25.769 34.597,26.041 35.058,26.041 v1(35.5,25.599)
P2.05: J70.11 R55.1 U4.6 | length 89.2
  Top Layer w0.127: U4.6@35.345,9.696 35.345,10.443 v2(35.5,10.599) ; v2(55.833,8.642) 56.428,8.642 57.279,9.493 84.586,9.493 85.988,10.895 85.988,39.569 87.08,40.661 J70.11@89.431,40.661
  L3 w0.127: v2(35.5,10.599) 36.737,9.362 38.615,9.362 39.534,8.443 55.634,8.443 v2(55.833,8.642)
  Bottom Layer w0.127: R55.1@34.809,9.477 34.809,9.831 34.27,10.37 34.27,10.904 34.477,11.111 34.988,11.111 v2(35.5,10.599) v2@35.45,10.548
P2.06: J70.13 R52.1 U3.7 | length 70.3
  Top Layer w0.125: v1(34.789,25.599) 34.945,25.443 U3.7@34.945,24.696 ; v2(86.407,26.906) 86.407,37.546 87.022,38.16 89.392,38.16 J70.13@89.431,38.121 J70.13@88.384,38.121
  L3 w0.125: v1(34.789,25.599) 35.847,24.541 83.986,24.541 86.35,26.906 v2(86.407,26.906)
  Bottom Layer w0.125: v1(34.789,25.599) 35.49,24.898 R52.1@35.49,24.528
P2.07: J70.15 R54.1 U4.7 | length 83
  Top Layer w0.124: v2(34.789,10.599) 34.945,10.443 U4.7@34.945,9.696
  Top Layer w0.125: v2(56.234,8.034) 57.289,9.089 84.853,9.089 86.404,10.64 86.404,21.52 87.368,22.484 87.368,34.624 88.325,35.581 J70.15@89.431,35.581
  L3 w0.127: v2(34.789,10.599) 36.393,8.995 38.464,8.995 39.425,8.034 v2(56.234,8.034)
  Bottom Layer w0.127: v2(34.789,10.599) 35.45,9.938 R54.1@35.45,9.477
P2.08: J70.19 U21.5 | length 52.1
  Top Layer w0.124: U21.5@45.871,45.405 47.622,43.654 47.622,40.692 53.215,35.099 56.738,35.099 v2(59.578,32.259) ; v2(89.426,31.329) 89.431,31.324 J70.19@89.431,30.501
  L3 w0.124: v2(59.578,32.259) 59.737,32.418 88.337,32.418 v2@89.431,31.324
P2.09: J70.17 U21.4 | length 53.9
  Top Layer w0.124: U21.4@42.771,45.405 43.017,45.405 43.061,45.361 43.061,44.07 43.483,43.648 44.213,43.648 53.09,34.772 56.453,34.772 v2(58.762,32.463) ; v2(89.431,32.19) J70.17@89.431,33.041
  L3 w0.124: v2(58.762,32.463) 58.974,32.674 88.947,32.674 v2(89.431,32.19)
P2.10/NFC_N: MOD1.87 R24.2 R70.1 | length 22.1
  Top Layer w0.127: R24.2@133.355,56.709 133.22,56.574 133.22,56.46 133.394,56.287 v2(133.408,56.287) 133.205,56.084 133.205,48.761 135.512,46.454 135.512,36.497 MOD1.87@135.709,36.3
  Bottom Layer w0.127: R70.1@133.4,55.856 133.408,55.864 v2(133.408,56.287)
P2.11/NFC_P: MOD1.84 R4.1 R25.2 | length 22.1
  Top Layer w0.127: R25.2@132.791,56.709 132.926,56.574 132.926,56.462 v2(132.754,56.291) 132.951,56.094 132.951,48.656 135.258,46.349 135.258,39.572 ; MOD1.84@135.059,36.3 135.258,36.499 135.258,39.538
  Bottom Layer w0.127: R4.1@132.754,55.856 v2(132.754,56.291)
P3V3: C2.2 C7.1 C8.1 C10.1 C11.1 C23.2 C25.2 C30.2 J59.2 J60.7 R3.2 R10.2 R90.1 U10.7 U14.5 U15.5 U21.7 U22.14 U23.B2 | length 64.9
  Top Layer w0.203: U21.7@45.871,46.405 C25.2@46.706,46.405
  Top Layer w0.254: U10.7@30.431,37.436 31.33,37.436 C23.2@31.343,37.449 31.668,37.449 32.397,38.178 v1(33.328,38.178) ; C2.2@38.234,36.675 C2.2@38.248,36.661 ; v1(38.265,36.083) 38.265,36.644 C2.2@38.248,36.661 ; U22.14@39.554,36.661 C2.2@38.248,36.661 ; U23.B2@39.773,45.468 39.887,45.354 C30.2@39.887,44.548 40.595,44.548 v1(40.608,44.561) ; J60.7@42.956,31.73 42.956,35.557 v1(42.961,35.562) ; C25.2@46.706,46.405 v1(47.424,46.405) 53.463,46.405 56.209,49.151 ; J59.2@55.865,51.374 55.865,49.495 56.209,49.151 ; R3.2@57.865,49.151 R10.2@56.831,49.151 56.209,49.151
  L3 w0.508: v1(40.608,44.561) 40.608,45.621 41.392,46.405 v1(47.424,46.405)
  L5 w0.508: v1(40.608,44.561) 42.961,42.208 v1(42.961,35.562)
  Bottom Layer w0.508: v1@24.941,37.904 v1(25.377,38.339) 26.327,39.289 32.912,39.289 v1(33.336,38.865) 33.328,38.856 v1(33.328,38.178) 35.422,36.083 v1(38.265,36.083) 38.787,35.562 v1(42.961,35.562)
  other v1: 24.951,37.894
P6.00/CK: MOD1.54 TP24.1 U11.B2 | length 16.7
  Top Layer w0.076: 128.109,34.675 MOD1.54@129.359,34.675
  Top Layer w0.127: v4(127.698,34.615) 127.758,34.675 128.109,34.675
  L3 w0.102: v2(123.803,40.079) 123.803,37.483 124.612,36.674 ccw(c124.684,36.746) 124.756,36.674 125.196,37.114 cw(c125.267,37.043) 125.339,37.114 cw(c125.267,37.043) 125.339,36.971 124.899,36.531 ccw(c124.971,36.459) 124.899,36.387 ccw(c124.971,36.459) 125.043,36.387 125.483,36.827 cw(c125.555,36.755) 125.627,36.827 cw(c125.555,36.755) 125.627,36.683 125.187,36.243 ccw(c125.258,36.172) 125.187,36.1 ccw(c125.258,36.172) 125.33,36.1 125.77,36.54 cw(c125.842,36.468) 125.914,36.54 cw(c125.842,36.468) 125.914,36.396 125.474,35.956 ccw(c125.546,35.884) 125.474,35.812 ccw(c125.546,35.884) 125.618,35.812 126.058,36.252 cw(c126.129,36.18) 126.201,36.252 cw(c126.129,36.18) 126.201,36.109 125.761,35.669 ccw(c125.833,35.597) 125.761,35.525 ccw(c125.833,35.597) 125.905,35.525 126.345,35.965 cw(c126.417,35.893) 126.489,35.965 cw(c126.417,35.893) 126.489,35.821 126.049,35.381 ccw(c126.121,35.309) 126.049,35.238 126.672,34.615 v4(127.698,34.615)
P6.01: MOD1.53 R96.2 TP28.1 | length 13.1
  Top Layer w0.102: 128.109,33.984 128.475,34.35 MOD1.53@128.559,34.35
  Top Layer w0.124: v2(127.373,34.081) 127.472,33.983 127.711,33.983 128.108,33.983 128.109,33.984 ; R96.2@128.689,44.863 128.818,44.734 v1(128.818,43.792)
  L5 w0.124: v2(127.373,34.081) 127.414,34.04 127.765,34.04 128.818,35.094 v1(128.818,43.792)
P6.02/RWDS: MOD1.55 TP21.1 U11.C3 | length 15.6
  Top Layer w0.127: v2(124.803,41.079) 125.218,40.664 125.218,38.134 125.074,37.991 124.424,37.991 ccw(c124.424,37.864) 124.297,37.864 ccw(c124.424,37.864) 124.424,37.737 125.091,37.737 cw(c125.091,37.61) 125.218,37.61 cw(c125.091,37.61) 125.091,37.483 124.424,37.483 ccw(c124.424,37.356) 124.297,37.356 ccw(c124.424,37.356) 124.424,37.229 125.091,37.229 cw(c125.091,37.102) 125.218,37.102 cw(c125.091,37.102) 125.091,36.975 124.424,36.975 ccw(c124.424,36.848) 124.297,36.848 ccw(c124.424,36.848) 124.424,36.721 125.091,36.721 cw(c125.091,36.594) 125.218,36.594 cw(c125.091,36.594) 125.091,36.467 124.424,36.467 ccw(c124.424,36.34) 124.297,36.34 ccw(c124.424,36.34) 124.424,36.213 125.117,36.213 cw(c125.117,36.086) 125.244,36.086 125.244,35.727 125.97,35 MOD1.55@128.559,35
P6.03/CS0: MOD1.51 R28.2 TP23.1 U11.C2 | length 17.7
  Top Layer w0.127: v2(124.803,40.079) 124.29,40.593 123.606,40.593 123.257,40.244 123.257,38.488 ccw(c123.389,38.488) 123.389,38.356 123.514,38.356 cw(c123.514,38.229) 123.641,38.229 cw(c123.514,38.229) 123.514,38.102 122.968,38.102 ccw(c122.968,37.975) 122.841,37.975 ccw(c122.968,37.975) 122.968,37.848 123.514,37.848 cw(c123.514,37.721) 123.641,37.721 cw(c123.514,37.721) 123.514,37.594 122.968,37.594 ccw(c122.968,37.467) 122.841,37.467 ccw(c122.968,37.467) 122.968,37.34 123.514,37.34 cw(c123.514,37.213) 123.641,37.213 cw(c123.514,37.213) 123.514,37.086 122.968,37.086 ccw(c122.968,36.959) 122.841,36.959 ccw(c122.968,36.959) 122.968,36.832 123.539,36.832 cw(c123.539,36.705) 123.666,36.705 123.666,36.199 126.298,33.567 128.426,33.567 MOD1.51@128.559,33.7
  Bottom Layer w0.127: R28.2@123.813,40.785 124.098,40.785 v2(124.803,40.079)
P6.04/DQ7: MOD1.52 TP34.1 U11.E1 | length 16.8
  L3 w0.102: v2(126.803,39.079) 127.304,39.079 128.013,38.37 128.013,38.065 cw(c127.912,38.065) 127.912,37.963 127.289,37.963 ccw(c127.289,37.862) 127.188,37.862 ccw(c127.289,37.862) 127.289,37.76 127.912,37.76 cw(c127.912,37.659) 128.013,37.659 cw(c127.912,37.659) 127.912,37.557 127.289,37.557 ccw(c127.289,37.455) 127.188,37.455 ccw(c127.289,37.455) 127.289,37.354 127.912,37.354 cw(c127.912,37.252) 128.013,37.252 cw(c127.912,37.252) 127.912,37.151 127.289,37.151 ccw(c127.289,37.049) 127.188,37.049 ccw(c127.289,37.049) 127.289,36.947 127.912,36.947 cw(c127.912,36.846) 128.013,36.846 cw(c127.912,36.846) 127.912,36.744 127.289,36.744 ccw(c127.289,36.643) 127.188,36.643 ccw(c127.289,36.643) 127.289,36.541 127.912,36.541 cw(c127.912,36.439) 128.013,36.439 cw(c127.912,36.439) 127.912,36.338 127.289,36.338 ccw(c127.289,36.236) 127.188,36.236 ccw(c127.289,36.236) 127.289,36.135 127.912,36.135 cw(c127.912,36.033) 128.013,36.033 cw(c127.912,36.033) 127.912,35.931 127.289,35.931 ccw(c127.289,35.83) 127.188,35.83 ccw(c127.289,35.83) 127.289,35.728 127.912,35.728 cw(c127.912,35.627) 128.013,35.627 cw(c127.912,35.627) 127.912,35.525 127.289,35.525 ccw(c127.289,35.423) 127.188,35.423 ccw(c127.289,35.423) 127.289,35.322 127.719,35.322 128.062,35.322 v3(129.359,34.025)
P6.05/DQ1: MOD1.56 TP26.1 U11.D2 | length 15.1
  Top Layer w0.127: v2(125.803,40.079) 125.803,39.622 126.255,39.17 126.255,38.146 126.577,37.823 126.577,37.686 cw(c126.45,37.686) 126.45,37.559 125.819,37.559 ccw(c125.819,37.432) 125.692,37.432 ccw(c125.819,37.432) 125.819,37.305 126.45,37.305 cw(c126.45,37.178) 126.577,37.178 cw(c126.45,37.178) 126.45,37.051 125.819,37.051 ccw(c125.819,36.924) 125.692,36.924 ccw(c125.819,36.924) 125.819,36.797 126.45,36.797 cw(c126.45,36.67) 126.577,36.67 cw(c126.45,36.67) 126.45,36.543 125.819,36.543 ccw(c125.819,36.416) 125.692,36.416 ccw(c125.819,36.416) 125.819,36.289 127.552,36.289 cw(c127.552,36.162) 127.679,36.162 cw(c127.552,36.162) 127.552,36.035 125.819,36.035 ccw(c125.819,35.908) 125.692,35.908 ccw(c125.819,35.908) 125.819,35.781 126.45,35.781 126.622,35.781 126.753,35.65 MOD1.56@128.559,35.65
P6.06/DQ6: MOD1.58 TP33.1 U11.E2 | length 14.7
  Top Layer w0.127: v2(126.803,40.079) 127.626,39.257 127.626,38.904 ccw(c127.758,38.904) 127.758,38.772 127.959,38.772 ; 127.985,38.772 cw(c127.985,38.645) 128.112,38.645 cw(c127.985,38.645) 127.985,38.518 127,38.518 ccw(c127,38.391) 126.873,38.391 ccw(c127,38.391) 127,38.264 127.985,38.264 cw(c127.985,38.137) 128.112,38.137 cw(c127.985,38.137) 127.985,38.01 127,38.01 ccw(c127,37.883) 126.873,37.883 ccw(c127,37.883) 127,37.756 127.985,37.756 cw(c127.985,37.629) 128.112,37.629 cw(c127.985,37.629) 127.985,37.502 127,37.502 ccw(c127,37.375) 126.873,37.375 ccw(c127,37.375) 127,37.248 128.01,37.248 cw(c128.01,37.121) 128.137,37.121 cw(c128.01,37.121) 128.01,36.994 127,36.994 ccw(c127,36.867) 126.873,36.867 ccw(c127,36.867) 127,36.74 128.256,36.74 128.307,36.791 129.069,36.791 129.209,36.651 MOD1.58@129.209,36.3
P6.07/DQ0: MOD1.60 TP25.1 U11.D3 | length 15.2
  Top Layer w0.127: v2(125.803,41.079) 126.393,41.67 127.023,41.67 127.396,41.296 127.785,41.296 127.975,41.487 cw(c128.065,41.397) 128.155,41.487 cw(c128.065,41.397) 128.155,41.307 127.709,40.861 ccw(c127.799,40.771) 127.709,40.681 ccw(c127.799,40.771) 127.888,40.681 128.334,41.127 cw(c128.424,41.038) 128.514,41.127 cw(c128.424,41.038) 128.514,40.948 128.068,40.502 ccw(c128.158,40.412) 128.068,40.322 ccw(c128.158,40.412) 128.248,40.322 128.694,40.768 cw(c128.783,40.678) 128.873,40.768 cw(c128.783,40.678) 128.873,40.589 128.427,40.143 ccw(c128.517,40.053) 128.427,39.963 ccw(c128.517,40.053) 128.607,39.963 129.053,40.409 cw(c129.143,40.319) 129.232,40.409 cw(c129.143,40.319) 129.232,40.229 128.786,39.783 ccw(c128.876,39.694) 128.786,39.604 ccw(c128.876,39.694) 128.966,39.604 129.357,39.995 cw(c129.447,39.905) 129.537,39.995 130.353,39.179 130.353,37.165 129.859,36.671 MOD1.60@129.859,36.3
P6.08/DQ5: MOD1.59 TP32.1 U11.E3 | length 15.4
  Top Layer w0.076: MOD1.59@129.534,35.5 129.534,36.75
  Top Layer w0.127: v2(126.803,41.079) 126.803,40.886 128.469,39.22 129.652,39.22 cw(c129.652,39.093) 129.779,39.093 cw(c129.652,39.093) 129.652,38.966 128.779,38.966 ccw(c128.779,38.839) 128.652,38.839 ccw(c128.779,38.839) 128.779,38.712 129.652,38.712 cw(c129.652,38.585) 129.779,38.585 cw(c129.652,38.585) 129.652,38.458 128.779,38.458 ccw(c128.779,38.331) 128.652,38.331 ccw(c128.779,38.331) 128.779,38.204 129.652,38.204 cw(c129.652,38.077) 129.779,38.077 cw(c129.652,38.077) 129.652,37.95 128.779,37.95 ccw(c128.779,37.823) 128.652,37.823 ccw(c128.779,37.823) 128.779,37.696 129.677,37.696 cw(c129.677,37.569) 129.804,37.569 cw(c129.677,37.569) 129.677,37.442 128.779,37.442 ccw(c128.779,37.315) 128.652,37.315 ccw(c128.779,37.315) 128.779,37.188 129.345,37.188 129.534,36.999 129.534,36.75
P6.09/DQ3: MOD1.62 TP29.1 U11.D4 | length 16.6
  L3 w0.102: v2(125.803,42.079) 126.213,41.67 126.9,41.67 129.28,39.29 129.28,39.031 cw(c129.178,39.031) 129.178,38.929 128.585,38.929 ccw(c128.585,38.828) 128.484,38.828 ccw(c128.585,38.828) 128.585,38.726 129.178,38.726 cw(c129.178,38.624) 129.28,38.624 cw(c129.178,38.624) 129.178,38.523 128.585,38.523 ccw(c128.585,38.421) 128.484,38.421 ccw(c128.585,38.421) 128.585,38.32 129.178,38.32 cw(c129.178,38.218) 129.28,38.218 cw(c129.178,38.218) 129.178,38.116 128.585,38.116 ccw(c128.585,38.015) 128.484,38.015 ccw(c128.585,38.015) 128.585,37.913 129.178,37.913 cw(c129.178,37.812) 129.28,37.812 cw(c129.178,37.812) 129.178,37.71 128.585,37.71 ccw(c128.585,37.608) 128.484,37.608 ccw(c128.585,37.608) 128.585,37.507 129.178,37.507 cw(c129.178,37.405) 129.28,37.405 cw(c129.178,37.405) 129.178,37.304 128.585,37.304 ccw(c128.585,37.202) 128.484,37.202 128.484,36.75 128.484,36.438 130.222,34.7 v3(130.509,34.7)
P6.10/DQ2: MOD1.64 TP27.1 U11.C4 | length 14.6
  Top Layer w0.076: MOD1.64@130.834,35.5 130.834,36.75
  Top Layer w0.127: v2(124.803,42.079) 124.803,42.179 125.184,42.56 128.623,42.56 129.657,41.526 cw(c129.567,41.437) 129.657,41.347 129.314,41.004 ccw(c129.404,40.914) 129.314,40.824 ccw(c129.404,40.914) 129.494,40.824 129.836,41.167 cw(c129.926,41.077) 130.016,41.167 ; 130.016,41.167 cw(c129.926,41.077) 130.016,40.988 129.673,40.645 ccw(c129.763,40.555) 129.673,40.465 ccw(c129.763,40.555) 129.853,40.465 130.196,40.808 cw(c130.285,40.718) 130.375,40.808 130.834,40.349 130.834,36.75
P6.11/DQ4: MOD1.61 TP31.1 U11.D5 | length 15.4
  L3 w0.102: v2(125.803,43.079) 127.054,43.079 128.168,41.965 cw(c128.097,41.894) 128.168,41.822 127.788,41.441 ccw(c127.86,41.37) 127.788,41.298 ccw(c127.86,41.37) 127.932,41.298 128.312,41.678 cw(c128.384,41.606) 128.456,41.678 cw(c128.384,41.606) 128.456,41.534 128.075,41.154 ccw(c128.147,41.082) 128.075,41.01 ccw(c128.147,41.082) 128.219,41.01 128.599,41.391 cw(c128.671,41.319) 128.743,41.391 cw(c128.671,41.319) 128.743,41.247 128.363,40.867 ccw(c128.435,40.795) 128.363,40.723 ccw(c128.435,40.795) 128.506,40.723 128.887,41.103 cw(c128.959,41.032) 129.03,41.103 cw(c128.959,41.032) 129.03,40.96 128.65,40.579 ccw(c128.722,40.508) 128.65,40.436 ccw(c128.722,40.508) 128.794,40.436 129.174,40.816 cw(c129.246,40.744) 129.318,40.816 129.906,40.227 129.906,36.307 130.184,36.029 v3(130.184,35.5)
P6.12/RESETN: MOD1.63 R23.2 TP22.1 U11.A4 | length 14.6
  L3 w0.102: v2(122.803,42.079) 122.803,42.432 123.863,43.492 127.08,43.492 130.509,40.063 130.509,36.75 v3(130.509,36.3)
  Bottom Layer w0.127: R23.2@121.901,42.125 121.946,42.079 v2(122.803,42.079)
P6.13: MOD1.65 R95.2 TP30.1 | length 11.2
  Top Layer w0.102: v2(131.142,34.111) 131.159,34.129 MOD1.65@131.159,34.7
  Top Layer w0.124: R95.2@130.026,43.908 130.097,43.837 v1(130.097,43.02)
  L5 w0.124: v1(130.097,43.02) 130.097,41.261 131.603,39.755 131.603,34.572 v2(131.142,34.111)
P7.00: J71.15 U22.4 | length 69.7
  Top Layer w0.127: U22.4@45.254,38.611 46.646,38.611 53.876,31.381 v2@53.876,22.408 ; v2(89.43,4.207) J71.15@89.431,5.584
  L3 w0.127: v2(53.881,22.403) 53.813,22.335 53.813,15.454 65.652,3.615 88.838,3.615 v2(89.43,4.207)
P7.01: J71.11 U22.5 | length 73.9
  Top Layer w0.127: U22.5@45.254,39.261 46.45,39.261 54.198,31.513 54.198,22.829 54.423,22.604 54.423,21.91 v2(54.303,21.79) ; v2(86.298,4) 86.298,8.648 88.314,10.664 J71.11@89.431,10.664
  L3 w0.127: v2(54.303,21.79) 54.108,21.595 54.108,15.692 65.859,3.94 86.238,3.94 v2(86.298,4)
P7.02: J71.13 U22.3 | length 72.4
  Top Layer w0.127: U22.3@45.254,37.961 46.787,37.961 53.545,31.204 53.545,22.773 53.289,22.517 v2(53.289,22.05) ; v2(86.97,3.169) 87.394,3.593 87.394,7.246 88.272,8.124 J71.13@89.431,8.124
  L3 w0.127: v2(53.289,22.05) 53.532,21.806 53.532,15.183 65.546,3.169 v2(86.97,3.169)
P7.03: J71.7 P16.12 | length 62.2
  Top Layer w0.127: J71.7@89.431,15.744 90.568,15.744 91.344,16.52 91.344,18.47 92.623,19.75 92.623,26.897 92.914,27.188 v2(92.914,28.842) ; P16.12@119.526,60.816 119.526,58.457 v2@119.535,58.448
  Bottom Layer w0.127: v2(92.914,28.842) 93.275,28.482 98.885,28.482 110.353,39.95 110.353,48.435 119.537,57.619 v2(119.537,58.446) v2@119.535,58.448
